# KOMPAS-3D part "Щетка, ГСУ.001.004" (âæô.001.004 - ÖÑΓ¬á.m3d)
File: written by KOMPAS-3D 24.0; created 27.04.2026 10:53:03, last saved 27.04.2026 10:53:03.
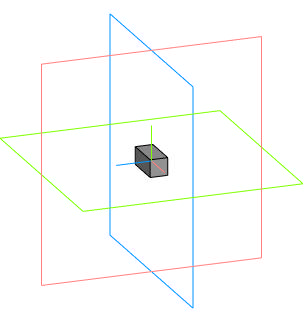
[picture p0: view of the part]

Document properties: Автор: User7; Полное имя файла: C:\Users\User7\Desktop\олимп\ГСУ.001.004 - Щетка.m3d

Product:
- Part/product: Щетка  | designation ГСУ.001.004
    Масса: 0.001131

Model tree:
1. Эскиз:1
2. Элемент выдавливания:1
     Расстояние 1 = 9

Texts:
  ГСУ.001.004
